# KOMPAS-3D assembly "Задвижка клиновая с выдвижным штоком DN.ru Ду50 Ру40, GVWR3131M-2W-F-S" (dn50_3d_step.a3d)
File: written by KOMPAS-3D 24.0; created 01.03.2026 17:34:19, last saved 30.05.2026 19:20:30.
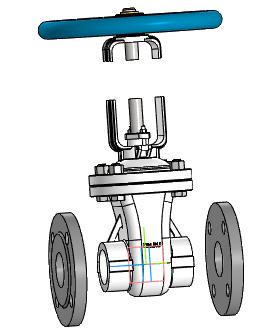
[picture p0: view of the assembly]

Document properties: Автор: R2D2; Полное имя файла: E:\Работа\Зайцев\GVWR3131M-2W-F-S Задвижка клиновая с выдвижным штоком DN.ru Ду50-100 Ру40\исходные материалы\DN50\dn50_3d_step.a3d

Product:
- Component [detail]: Деталь2  | qty 1  | pos. 1  | Масса: 3.95529; Автор: R2D2; additional columns: Типовые; source file: Деталь2 Деталь2.m3d
- Component [detail]: AS 1110 - M12 x 45  | qty 4  | pos. 2  | Масса: 0.056439; Комментарий: Болты и винты   шестигранные точные   метрические ISO; Автор: R2D2; additional columns: Сталь, мягкая; source file: AS 1110 - M12 x 45 AS 1110 - M12 x 45.m3d
- Component [detail]: ANSI B18.2.4.2M - M12x1,75 - 18  | designation ANSI B18.2.4.2M - M12x1,75  | qty 4  | pos. 3  | Масса: 0.018772; Комментарий: Типы метрических   шестигранных гаек   2; Автор: R2D2; additional columns: Сталь, мягкая; source file: ANSI B18.2.4.2M - M12x1,75 ANSI B18.2.4.2M - M12x1,75 - 18.m3d
- Component [detail]: ANSI B18.2.4.2M - M5x0,8 - 8  | designation ANSI B18.2.4.2M - M5x0,8  | qty 1  | pos. 4  | Масса: 0.00167; Комментарий: Типы метрических   шестигранных гаек   2; Автор: R2D2; additional columns: Сталь, мягкая; source file: ANSI B18.2.4.2M - M5x0,8 ANSI B18.2.4.2M - M5x0,8 - 8.m3d
- Component [detail]: Деталь1  | qty 1  | pos. 5  | Масса: 12.23036; Автор: R2D2; additional columns: Типовые; source file: 2.m3d
- Component [detail]: ФЛАНЕЦ  | designation Деталь1  | qty 1  | pos. 5  | Масса: 2.444901; Автор: R2D2; additional columns: Типовые; source file: 1.m3d
- Component [detail]: ФЛАНЕЦ  | designation Деталь1-01  | qty 1  | pos. 6  | Масса: 2.444901; Автор: R2D2; additional columns: Типовые; source file: 1.m3d
- Component [detail]: ANSI B18.2.4.2M - M5x0,8 - 8  | designation ANSI B18.2.4.2M - M5x0,8-01  | qty 1  | pos. 7  | Масса: 0.00167; Комментарий: Типы метрических   шестигранных гаек   2; Автор: R2D2; additional columns: Сталь, мягкая; source file: ANSI B18.2.4.2M - M5x0,8 ANSI B18.2.4.2M - M5x0,8 - 8.m3d
- Component [detail]: Деталь1  | qty 1  | Масса: 0.395685; Автор: R2D2; additional columns: Типовые; source file: 3.m3d
- Part/product: Задвижка клиновая с выдвижным штоком DN.ru Ду50 Ру40  | designation GVWR3131M-2W-F-S
    Масса: 12
    Раздел спецификации: Прочие изделия
    Примечание: D040-08605

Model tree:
1. Массив по концентрической сетке:1  (with: Грань.Элемент вращения:1)  (labels: Грань.Твердое тело1; Грань.Solid1)  (4 pattern instances)
     Шаг 2 = 360; Расстояние = -125; Ориентация = 2; Ориентация = 2; Расстояние = -362.5

Referenced files in E:\Работа\Зайцев\GVWR3131M-2W-F-S Задвижка клиновая с выдвижным штоком DN.ru Ду50-100 Ру40\исходные материалы\DN50\: Деталь2 Деталь2.m3d, AS 1110 - M12 x 45 AS 1110 - M12 x 45.m3d, ANSI B18.2.4.2M - M12x1,75 ANSI B18.2.4.2M - M12x1,75 - 18.m3d, ANSI B18.2.4.2M - M5x0,8 ANSI B18.2.4.2M - M5x0,8 - 8.m3d, 3.m3d, 1.m3d, 2.m3d
Referenced files in E:\Работа\Зайцев\GVWR3131M-2W-F-S Задвижка клиновая с выдвижным штоком DN.ru Ду50-200 Ру63\DN50\исходные материалы\: ANSI B18.2.4.2M - M12x1,75 ANSI B18.2.4.2M - M12x1,75 - 18.m3d, AS 1110 - M12 x 45 AS 1110 - M12 x 45.m3d
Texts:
  Программные изделия  и базы данных
  ANSI B18.2.4.2M - M12x1,75
  ANSI B18.2.4.2M - M5x0,8
  Деталь1 - 01
  Деталь1-01
  ANSI B18.2.4.2M - M5x0,8 - 01
  ANSI B18.2.4.2M - M5x0,8-01
  GVWR3131M-2W-F-S
  Деталь2 Деталь2
  AS 1110 - M12 x 45 AS 1110 - M12 x 45 (1)
  ANSI B18.2.4.2M - M12x1,75 ANSI B18.2.4.2M - M12x1,75 - 18 (1)
  ANSI B18.2.4.2M - M5x0,8 ANSI B18.2.4.2M - M5x0,8 - 8
  Деталь1 Деталь1
  Деталь1 ФЛАНЕЦ
  Деталь1-01 ФЛАНЕЦ
  ANSI B18.2.4.2M - M12x1,75 ANSI B18.2.4.2M - M12x1,75 - 18 (2)
  AS 1110 - M12 x 45 AS 1110 - M12 x 45 (2)
  ANSI B18.2.4.2M - M12x1,75 ANSI B18.2.4.2M - M12x1,75 - 18 (3)
  AS 1110 - M12 x 45 AS 1110 - M12 x 45 (3)
  ANSI B18.2.4.2M - M12x1,75 ANSI B18.2.4.2M - M12x1,75 - 18 (4)
  AS 1110 - M12 x 45 AS 1110 - M12 x 45 (4)
  ANSI B18.2.4.2M - M5x0,8-01 ANSI B18.2.4.2M - M5x0,8 - 8
  Ось Y.Начало координат
  Ось Z.Начало координат
  Плоскость ZX.Начало координат
  Плоскость XY.Начало координат
  Плоскость ZY.Начало координат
